// Mitsubishi GX Works2 project: 10.星三角延时启动   PLC: FX3U/FX3UC

PROGRAM MAIN
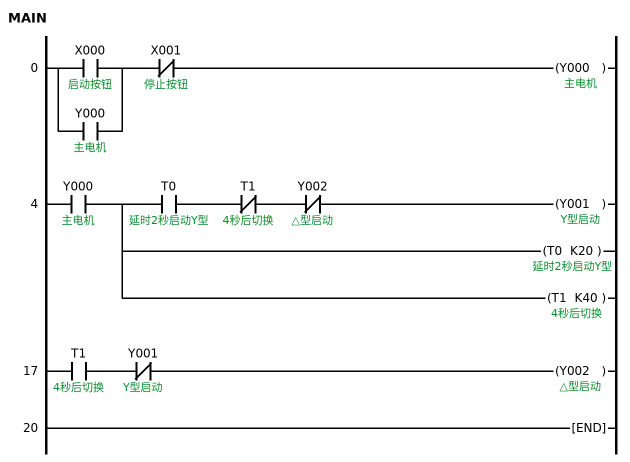
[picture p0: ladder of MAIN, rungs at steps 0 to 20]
0     LD      X000  ; 启动按钮
      OR      Y000  ; 主电机
      ANI     X001  ; 停止按钮
      OUT     Y000  ; 主电机
4     LD      Y000  ; 主电机
      MPS
      AND     T0  ; 延时2秒启动Y型
      ANI     T1  ; 4秒后切换
      ANI     Y002  ; △型启动
      OUT     Y001  ; Y型启动
      MPP
      OUT     T0 K20  ; 延时2秒启动Y型
      OUT     T1 K40  ; 4秒后切换
17    LD      T1  ; 4秒后切换
      ANI     Y001  ; Y型启动
      OUT     Y002  ; △型启动
20    END
END_PROGRAM
